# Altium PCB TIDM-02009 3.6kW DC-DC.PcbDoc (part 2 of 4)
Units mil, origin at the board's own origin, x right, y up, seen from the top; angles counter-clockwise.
Board outline 11220.47 x 8463 mil, 4 copper layers (Top Layer, Signal Layer 1, Signal Layer 2, Bottom Layer), stack 109.77 mil thick; 298 components, 250 nets, 959 pads, 2937 vias.
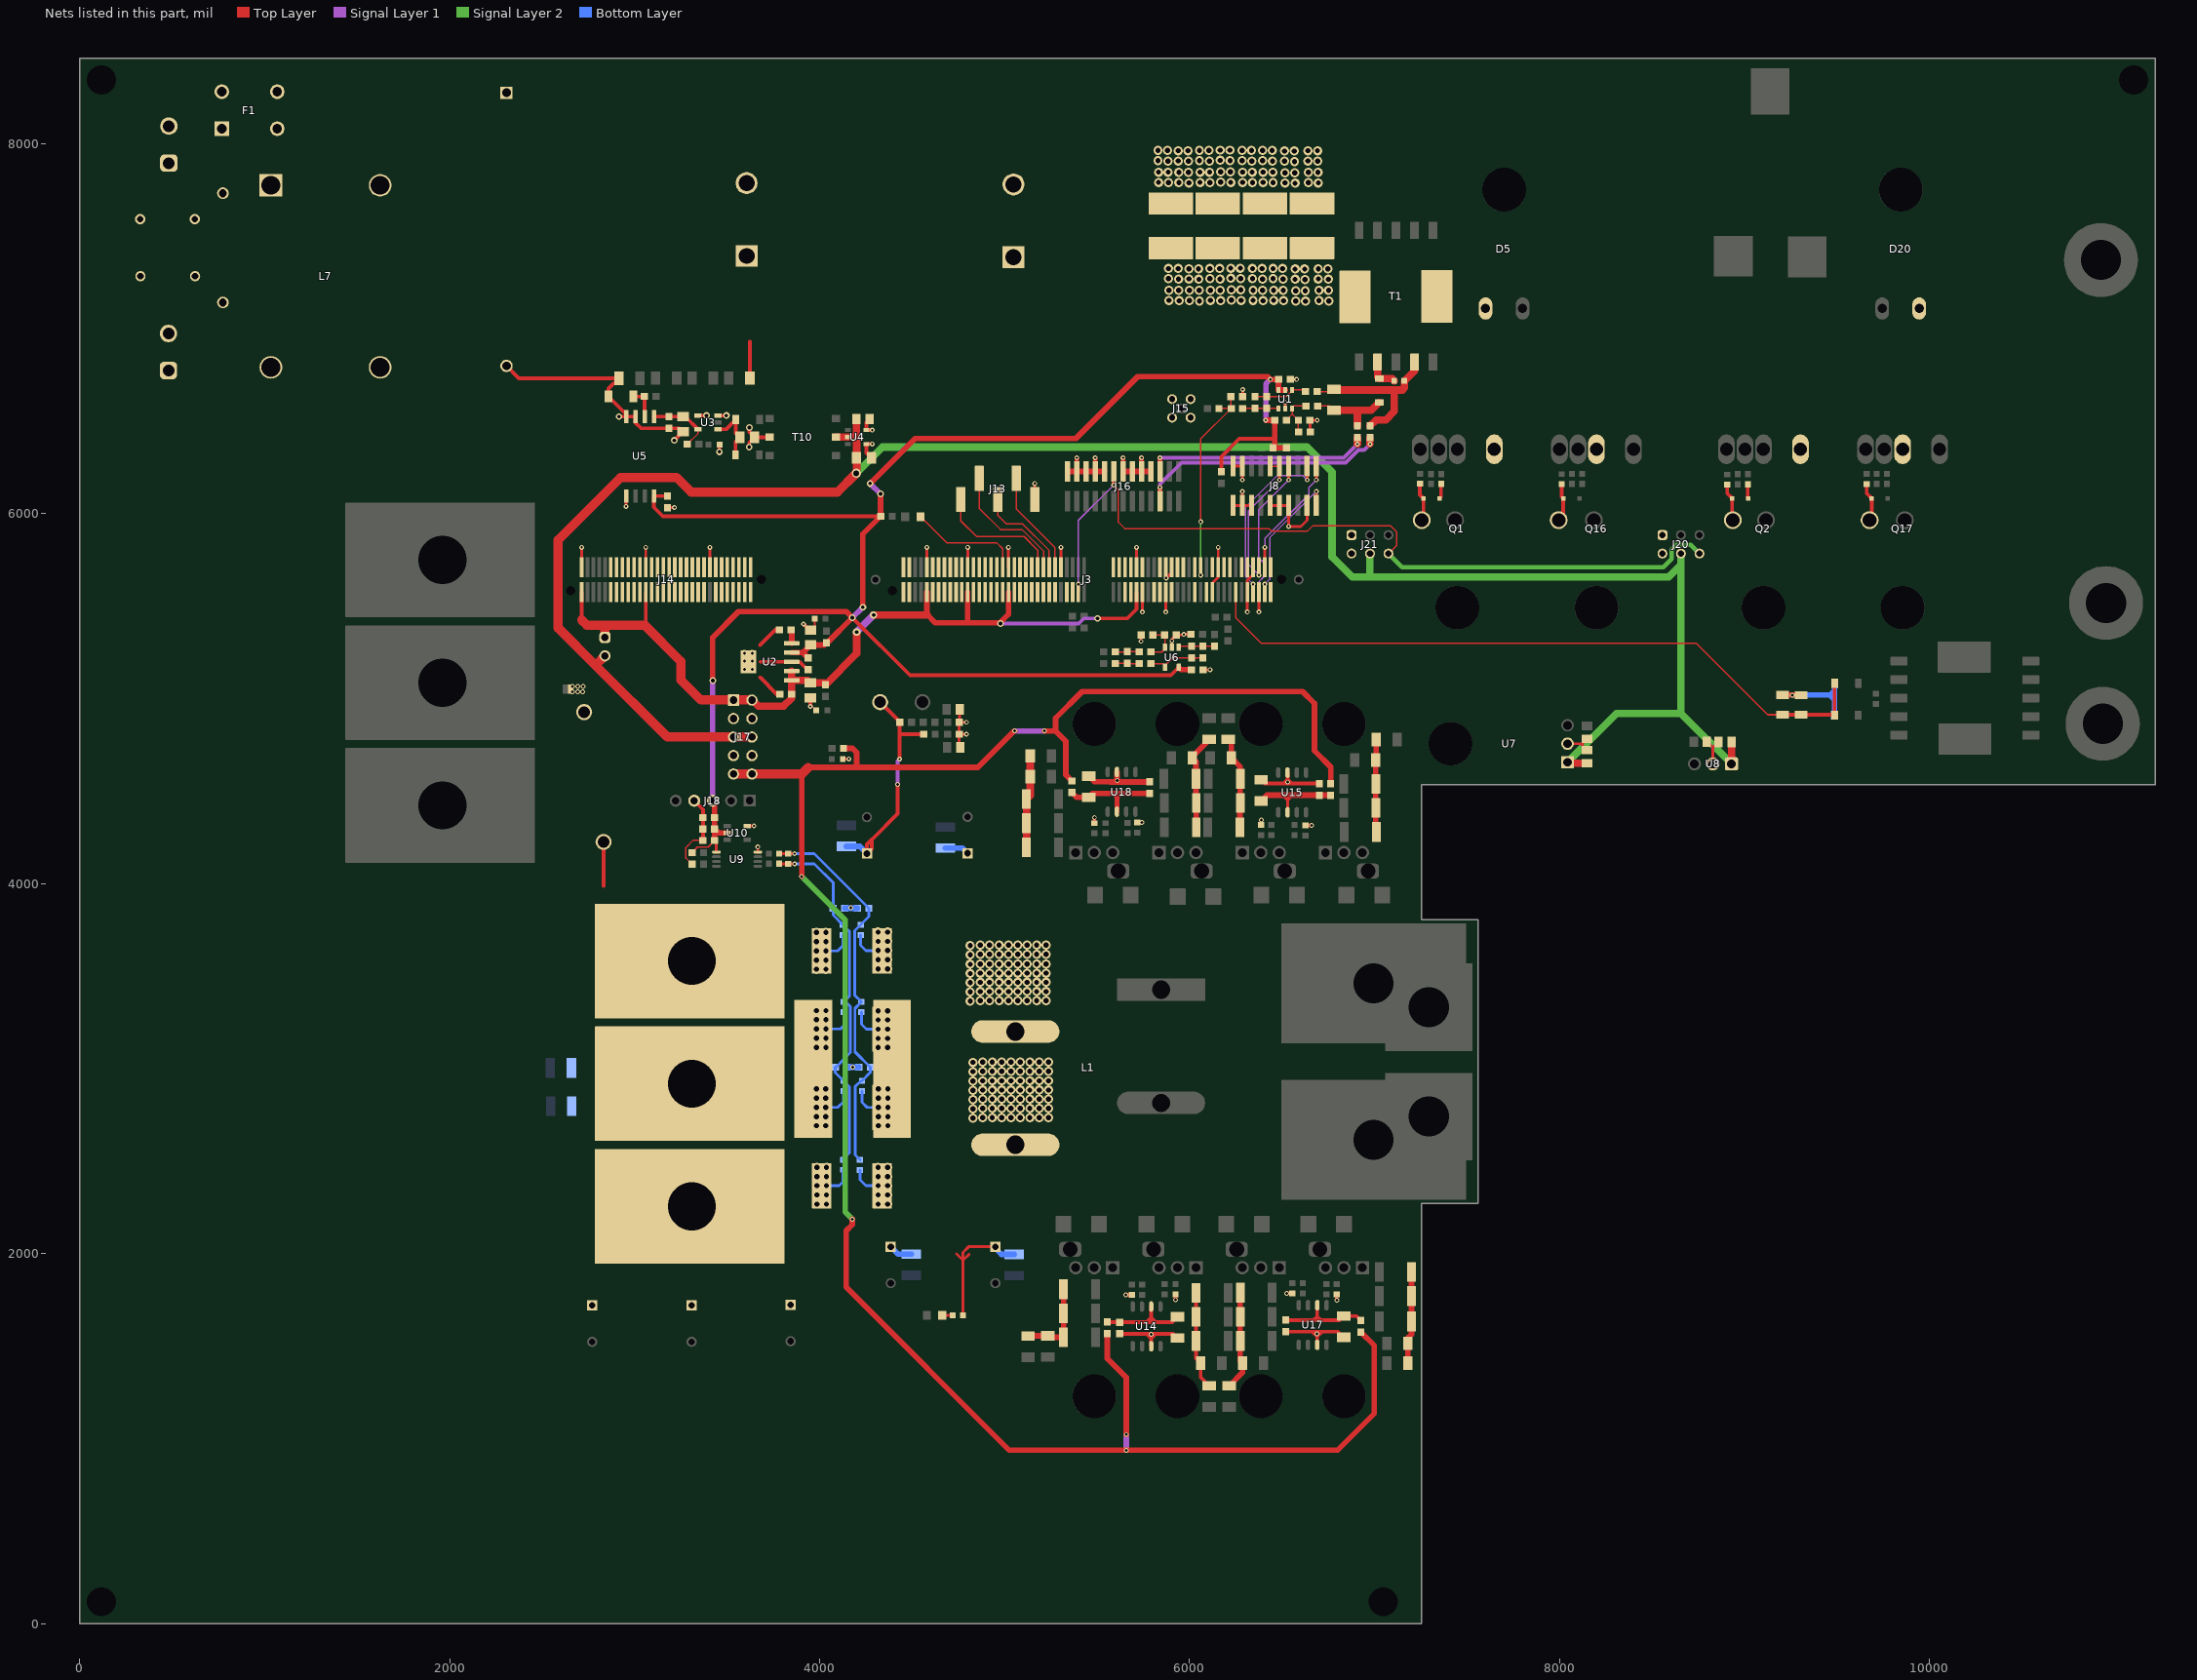
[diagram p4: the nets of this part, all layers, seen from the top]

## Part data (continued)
C52 C54 C55: library part CMP-0006982-4, "CAP, CERM, 220 pF, 50 V, +/- 10%, X7R, 0603", Cap_Case=0603, Manufacturer=Kemet, Supplier Part Number 1=399-5342-1-ND, TempCo=X7R, Tolerance_%=10%, Value1=Unknown, Value2=50V, ValueDisplayed=220pF
C64: library part CMP-0007143-4, "CAP, CERM, 0.01 uF, 50 V, +/- 10%, X7R, AEC-Q200 Grade 1, 0603", Cap_Case=0603, Manufacturer=MuRata, Supplier Part Number 1=490-4778-1-ND, TempCo=X7R, Tolerance_%=10%, Value1=Unknown, Value2=50V, ValueDisplayed=0.01uF
C65 C67 C73 C75: "CAP, CERM, 0.1 µF, 25 V,+/- 10%, X7R, AEC-Q200 Grade 1, 0603", Cap_Case=0603, Manufacturer=TDK, Supplier Part Number 1=445-5667-1-ND, TempCo=X7R, Tolerance_%=10, Value2=25V, ValueDisplayed=0.1µF
C66 C68 C74 C76: "CAP, CERM, 4.7 µF, 50 V, +/- 10%, X5R, 1206", Cap_Case=1206, Manufacturer=MuRata, Supplier Part Number 1=1845761, TempCo=X5R, Tolerance_%=10, Value1=Unknown, Value2=50V, ValueDisplayed=4.7µF
C83 C84: library part CMP-0083862-1, "CAP, AL, 120 µF, 600 V, +/- 20%, TH", Cap_Case=35x35mm, Manufacturer=Nichicon, Tolerance_%=20%, Value2=600V, ValueDisplayed=120µF
D1: "LED, Red, SMD", Color=Red, Manufacturer="Wurth Elektronik", Power_TotalModule=0.072, Supplier Part Number 1=732-4985-1-ND, Value1=0.072W, Value2=1.9V
D2: library part CMP-0029001-2, "Diode, Ultrafast, 100 V, 0.15 A, SOD-123", Manufacturer="Diodes Inc.", Value1=0.15A, Value2=1.25V
D3 D4 D18 D19: "Diode, Schottky, 40 V, 0.5 A, SOD-323", Manufacturer=Toshiba, Supplier Part Number 1=CUS05S40H3FCT-ND, Value1=0.5A, Value2=0.6V
D5 D20: library part CMP-0088257-2, "Diode Silicon Carbide Schottky 650V 37A (DC) Through Hole TO-220-2", Manufacturer=Wolfspeed
D6 D7 D8 D9 D10 D11 D12 D13: library part CMP-0087693-1, "70.1V Clamp 8.7A Ipp Tvs Diode Surface Mount DO-214AA (SMBJ)", Manufacturer=Littelfuse
D14 D15 D16 D17: library part 1N4148W-7-F, "Diode, Ultrafast, 100 V, 0.15 A, SOD-123", Manufacturer="Diodes Inc.", Supplier Part Number 1=1N4148W-FDICT-ND, Value1=0.15A, Value2=1.25V
D21 D27: library part CMP-0028526-1, "Diode, Schottky, 40 V, 0.5 A, SOD-123", Manufacturer="ON Semiconductor", Supplier Part Number 1=MBR0540T1GOSCT-ND, Value1=0.5A, Value2=0.51V
D22: library part CMP-0002951-1, "LED, Red, SMD", Color=Red, Manufacturer="Wurth Elektronik", Power_TotalModule=72mW, Supplier Part Number 1=732-4985-1-ND, Value1=0.072W, Value2=1.9V
D23 D24 D25 D26: library part CMP-0079921-1, "LED, Green, SMD", Color=Green, Manufacturer=Lite-On, Supplier Part Number 1=160-1828-1-ND, Value1=W, Value2=2V
F1: library part CMP-0088902-1, "FUSE HLDR CARTRIDGE 500V 16A PCB", Digikey Part Number=486-1160-ND, Fuse Current=16A, Manufacturer=Schurter, Mouser Part Number=693-3101.0045, Operating Temperature Range=to
"High Voltage1" "High Voltage2": library part CMP-0074835-1, "IEC 61010-1 High Voltage Warning"
J1 J2: library part CMP-0084907-1, "Terminal Block, 2 Pos, 5.08mm, Tin, TH", Color=Green, Current_A=20A, Manufacturer="Wurth Elektronik", Voltage_V=300V
J3: library part CMP-0003814-2, "C2000 controlCARD-120HSEC connector, SMT", Manufacturer=Samtec
J4 J5 J6 J7 J9 J10 J11 J12: library part CMP-0055026-1, Manufacturer=Mill-Max, Supplier Part Number 1=0312-015153427100-ND
J8: library part CMP-0075640-2, "Header, 1.27mm, 10x2, Tin, SMT", Color=Black, Current_A=3.1A, Manufacturer=Samtec, Supplier Part Number 1=SAM8792-ND
J13: library part CMP-0081122-1, "Header, 2.54mm, 5x1, Gold with Tin tail, SMT", Color=Black, Current_A=5.4A, Manufacturer=Samtec, Supplier Part Number 1=SAM12233-ND, Voltage_V=475V
J14: library part CMP-0003859-2, "C2000 controlCARD-180HSEC (60-pin addon) connector, SMT", Manufacturer=Samtec
J15: library part CMP-0088318-1, "MMCX Connector Jack, Female Socket 50Ohm Through Hole, Right Angle Solder", Dielectric Material=PTFE, Digikey Part Number=SAM10615-ND, Frequency_Fixed=6GHz, Manufacturer=Samtec, Mouser Part Number=200-MMCXJPHRATH1, Operating Temperature Range="-65°C to +125°C"
J16: library part CMP-0089180-1, Current_A=3.4A, Digikey Part Number=SAM9460-ND, Manufacturer=Samtec, Mouser Part Number=200-FTSH11301FDVK, Operating Temperature Range="-55°C to +125°C"
J17: library part CMP-0075665-2, "Header, 2.54mm, 5x2, Gold, Black, TH", Color=Black, Manufacturer=Samtec, Supplier Part Number 1=SAM8999-ND
J18: library part CMP-0075411-1, "Header, 100mil, 5x1, Gold, TH", Color=Black, Current_A=6.3A, Manufacturer=Samtec, Supplier Part Number 1=SAM1029-05-ND, Voltage_V=550V
J19: library part CMP-0084558-1, "Header, 2.54mm, 2x1, Tin, TH", Color=Black, Current_A=6.3A, Manufacturer=Samtec, Voltage_V=550V
J20 J21: library part CMP-0082603-1, "Receptacle, 2.54mm, 3x2, Tin, TH", Color=Green, Manufacturer="TE Connectivity", Supplier Part Number 1=A106656-ND
L1: library part CMP-0088176-1, "Fixed Inductor of Cyntec", Manufacturer=Cyntec
L2: library part CMP-0060854-1, "Inductor, Shielded E Core, Ferrite, 4.7 uH, 30 A, 0.00186 ohm, SMD", Manufacturer=Coilcraft, Value1="0.00186 ohm", Value2=30A, ValueDisplayed=4.7uH
L3 L4 L5 L6: "Ferrite Bead, 120 ohm @ 100 MHz, 0.5 A, 0603", Manufacturer="Wurth Elektronik", Supplier Part Number 1=732-1594-1-ND, Value1="0.3 ohm", Value2=0.5A, ValueDisplayed="120 ohm"
L7: "CMC 2.5MH 25A 2LN TH", Manufacturer="Wurth Elektronik", PartNumber=7448052502, Supplier Part Number 1=732-5600-ND, ValueDisplayed=2.5mH
LBL1: library part CMP-0003625-1, "Thermal Transfer Printable Labels, 0.650\" W x 0.200\" H - 10,000 per roll", Manufacturer=Brady, Supplier Part Number 1=97C5133
NT1: library part CMP-0078142-2, "Single point connection between nets.", Manufacturer=N/A
Q1 Q2 Q16 Q17: library part CMP-0088256-2, "SiC N-Channel MOSFET, 35 A, 1000 V C3M, 4-Pin TO-247", Manufacturer=Wolfspeed
R1: "RES, 13.0 k, 1%, 0.1 W, 0603", Manufacturer="Yageo America", Power_W=0.1, Supplier Part Number 1=311-13.0KHRCT-ND, TempCo="200 ppm/C", Tolerance_%=1, Value1=1%, Value2=0.1W, Value_Code=13k0, ValueDisplayed=13.0k
R2 R3 R4 R5 R15 R17 R18 R20: "RES, 10.0, 1%, 0.1 W, 0603", Manufacturer=Vishay-Dale, Power_W=0.1, Supplier Part Number 1=541-10.0HCT-ND, TempCo="100 ppm/C", Tolerance_%=1, Value1=1%, Value2=0.1W, Value_Code=10R0, ValueDisplayed=10.0
R6 R7 R8 R9: library part CMP-0087912-1, "500 µOhms ±1% 9W Chip Resistor Nonstandard Current Sense, Pulse Withstanding", Manufacturer=Cyntec, Power_W=9W, TempCo=75ppm/°C, Tolerance_%=1%
R10 R13: "RES, 0, 5%, 0.1 W, 0603", Manufacturer=Vishay-Dale, Power_W=0.1, Supplier Part Number 1=541-0.0GCT-ND, TempCo="200 ppm/C", Tolerance_%=5, Value1=5%, Value2=0.1W, Value_Code=0000, ValueDisplayed=0
R11: library part CMP-0087913-1, "125uOhm, 15W, high power, low ESL current shunt resistor", Manufacturer=Cyntec, Power_W=15W, TempCo=100ppm/°C, Tolerance_%=1%
R12 R68 R74 R79 R83 R87 R91 R92: library part CMP-0081973-1, "RES, 0, 0%, 0.25 W, AEC-Q200 Grade 0, 0603", Manufacturer=Vishay-Dale, Power_W=250mW, Supplier Part Number 1=541-2779-1-ND, Tolerance_%=0%, Value2=0.25W, Value_Code=0
R14 R43: "RES, 100 k, 1%, 0.1 W, 0603", Manufacturer=Vishay-Dale, Power_W=0.1, Supplier Part Number 1=541-100KHCT-ND, TempCo="100 ppm/C", Tolerance_%=1, Value1=1%, Value2=0.1W, Value_Code=100k
R16: library part CMP-0022679-3, "RES, 100, 1%, 0.1 W, AEC-Q200 Grade 0, 0603", Manufacturer=Panasonic, Power_W=100mW, Supplier Part Number 1=P100HCT-ND, TempCo="100 ppm/C", Tolerance_%=1%, Value2=0.1W, Value_Code=100R, ValueDisplayed=100
R19 R39: library part CMP-0023153-5, "RES, 4.70 k, 1%, 0.1 W, 0603", Manufacturer=Yageo, Power_W=100mW, Supplier Part Number 1=311-4.70KHRCT-ND, TempCo="100 ppm/C", Tolerance_%=1%, Value2=0.1W, Value_Code=4k70, ValueDisplayed=4.70k
R21 R22 R64 R65: "RES, 5.11, 1%, 0.1 W, 0603", Manufacturer=Vishay-Dale, Power_W=0.1, Supplier Part Number 1=541-5.11HHCT-ND, TempCo="100 ppm/C", Tolerance_%=1, Value1=1%, Value2=0.1W, Value_Code=5R11, ValueDisplayed=5.11
R23 R24 R69 R70: "RES, 1.00, 1%, 0.1 W, 0603", Manufacturer="Yageo America", Power_W=0.1, Supplier Part Number 1=311-1.00HRCT-ND, TempCo="200 ppm/C", Tolerance_%=1, Value1=1%, Value2=0.1W, Value_Code=1R00, ValueDisplayed=1.00
R25 R26 R71 R72 R157 R158 R159 R160 R172 R173 R174 R175: "RES, 10.0 k, 1%, 0.1 W, 0603", Manufacturer=Vishay-Dale, Power_W=0.1, Supplier Part Number 1=541-10.0KHCT-ND, TempCo="100 ppm/C", Tolerance_%=1, Value1=1%, Value2=0.1W, Value_Code=10k0, ValueDisplayed=10.0k
R27 R28 R29 R30 R31 R32 R33 R34 R35 R36 R37 R38 R44 R45 R46 R47 R48 R49 R50 R51 R52 R53 R54 R55: "RES, 30, 5%, 0.75 W, AEC-Q200 Grade 0, 2010", Manufacturer=Vishay-Dale, Power_W=0.75, Supplier Part Number 1=541-30.0WCT-ND, TempCo="200 ppm/C", Tolerance_%=5, Value1=5%, Value2=0.75W, Value_Code=30R0, ValueDisplayed=30
R40 R59: library part CMP-0023143-5, "RES, 49.9, 1%, 0.1 W, 0603", Manufacturer=Yageo, Power_W=100mW, Supplier Part Number 1=311-49.9HRCT-ND, TempCo="100 ppm/C", Tolerance_%=1%, Value2=0.1W, Value_Code=49R9, ValueDisplayed=49.9
R41 R56 R67: library part CMP-0022895-5, "RES, 1.00 k, 1%, 0.1 W, 0603", Manufacturer=Yageo, Power_W=100mW, Supplier Part Number 1=311-1.00KHRCT-ND, TempCo="100 ppm/C", Tolerance_%=1%, Value2=0.1W, Value_Code=1k00, ValueDisplayed=1.00k
R42 R57 R88 R95 R96 R140: library part CMP-0022746-5, "RES, 10.0 k, 1%, 0.1 W, 0603", Manufacturer=Yageo, Power_W=100mW, Supplier Part Number 1=311-10.0KHRCT-ND, TempCo="100 ppm/C", Tolerance_%=1%, Value2=0.1W, Value_Code=10k0, ValueDisplayed=10.0k
R58: library part CMP-0022751-4, "RES, 10.0, 1%, 0.1 W, 0603", Manufacturer=Yageo, Power_W=100mW, Supplier Part Number 1=311-10.0HRCT-ND, TempCo="100 ppm/C", Tolerance_%=1%, Value2=0.1W, Value_Code=10R0, ValueDisplayed=10.0
R60 R61: library part CMP-0018067-2, "RES, 20.0, 1%, 0.25 W, 1206", Manufacturer="Yageo America", Power_W=250mW, Supplier Part Number 1=311-20.0FRCT-ND, TempCo="100 ppm/C", Tolerance_%=1%, Value2=0.25W, Value_Code=20R0, ValueDisplayed=20.0
R62: library part CMP-0017094-3, "RES, 5.36, 1%, 0.25 W, AEC-Q200 Grade 0, 1206", Manufacturer=Vishay-Dale, Power_W=250mW, Supplier Part Number 1=541-5.36FFCT-ND, TempCo="100 ppm/C", Tolerance_%=1%, Value2=0.25W, Value_Code=5R36, ValueDisplayed=5.36
R63 R86: library part CMP-0022982-5, "RES, 2.15 k, 1%, 0.1 W, 0603", Manufacturer=Yageo, Power_W=100mW, Supplier Part Number 1=311-2.15KHRCT-ND, TempCo="100 ppm/C", Tolerance_%=1%, Value2=0.1W, Value_Code=2k15, ValueDisplayed=2.15k
R66: library part CMP-0022692-3, "RES, 22.0 k, 1%, 0.1 W, AEC-Q200 Grade 0, 0603", Manufacturer=Panasonic, Power_W=100mW, Supplier Part Number 1=P22.0KHCT-ND, TempCo="100 ppm/C", Tolerance_%=1%, Value2=0.1W, Value_Code=22k0, ValueDisplayed=22.0k
R73: library part CMP-0022865-5, "RES, 1.05 k, 1%, 0.1 W, 0603", Manufacturer=Yageo, Power_W=100mW, Supplier Part Number 1=311-1.05KHRCT-ND, TempCo="100 ppm/C", Tolerance_%=1%, Value2=0.1W, Value_Code=1k05, ValueDisplayed=1.05k
R75: library part CMP-0021989-3, "RES, 4.99 k, 1%, 0.1 W, 0603", Manufacturer=Bourns, Power_W=100mW, Supplier Part Number 1=CR0603-FX-4991ELFTR-ND, TempCo="100 ppm/C", Tolerance_%=1%, Value2=0.1W, Value_Code=4k99, ValueDisplayed=4.99k
R76 R77 R78: library part CMP-0017741-3, "RES, 845 k, 1%, 0.25 W, AEC-Q200 Grade 0, 1206", Manufacturer=Panasonic, Power_W=250mW, Supplier Part Number 1=P845KFCT-ND, TempCo="100 ppm/C", Tolerance_%=1%, Value2=0.25W, Value_Code=845k
R80: library part CMP-0017754-3, "RES, 9.09 k, 1%, 0.25 W, AEC-Q200 Grade 0, 1206", Manufacturer=Panasonic, Power_W=250mW, Supplier Part Number 1=P9.09KFCT-ND, TempCo="100 ppm/C", Tolerance_%=1%, Value2=0.25W, Value_Code=9k09, ValueDisplayed=9.09k
R81 R94: library part CMP-0022816-5, "RES, 15.0 k, 1%, 0.1 W, 0603", Manufacturer=Yageo, Power_W=100mW, Supplier Part Number 1=311-15.0KHRCT-ND, TempCo="100 ppm/C", Tolerance_%=1%, Value2=0.1W, Value_Code=15k0, ValueDisplayed=15.0k
R82 R84 R85 R93: library part CMP-0023151-5, "RES, 4.64 k, 1%, 0.1 W, 0603", Manufacturer=Yageo, Power_W=100mW, Supplier Part Number 1=311-4.64KHRCT-ND, TempCo="100 ppm/C", Tolerance_%=1%, Value2=0.1W, Value_Code=4k64, ValueDisplayed=4.64k
R89: library part CMP-0023250-5, "RES, 6.49 k, 1%, 0.1 W, 0603", Manufacturer=Yageo, Power_W=100mW, Supplier Part Number 1=311-6.49KHRCT-ND, TempCo="100 ppm/C", Tolerance_%=1%, Value2=0.1W, Value_Code=6k49, ValueDisplayed=6.49k
R90: library part CMP-0022684-3, "RES, 10.0 k, 1%, 0.1 W, 0603", Manufacturer=Panasonic, Power_W=100mW, Supplier Part Number 1=P10.0KHCT-ND, TempCo="100 ppm/C", Tolerance_%=1%, Value2=0.1W, Value_Code=10k0, ValueDisplayed=10.0k
R152 R153 R155 R156 R168 R169 R170 R171: "RES, 2.21, 1%, 0.1 W, 0603", Manufacturer=Vishay-Dale, Power_W=0.1, Supplier Part Number 1=541-2.21HHCT-ND, TempCo="100 ppm/C", Tolerance_%=1, Value1=1%, Value2=0.1W, Value_Code=2R21, ValueDisplayed=2.21
SR1 SR2 SR3 SR4 SR5 SR6 SR7 SR8: library part CMP-0087973-1, "MOSFET N-CH TO220-3", Manufacturer="Infineon Technologies"
T1 T8: library part CMP-0085494-1, "Current Sense Transformer, 8.5 mH, 254 Vµs, 40 A, AEC-Q200 Grade 1, SMT", Manufacturer=Coilcraft, ValueDisplayed=8.5mH
T2 T3 T4 T5 T7 T9: library part CMP-0077156-1, "Terminal 125A Lug", Current_A=125A, Manufacturer=Panduit, Supplier Part Number 1=298-11598-ND, Voltage_V=600V
T10: library part CMP-0030718-1, "Transformer, 475uH, SMT", Manufacturer="Wurth Elektronik", Supplier Part Number 1=732-4458-1-ND, ValueDisplayed=475uH
TP1 TP4: library part CMP-0055142-1, "Test Point, Compact, Red, TH", Color=Red, Manufacturer=Keystone, Supplier Part Number 1=36-5005-ND
TP2 TP3: library part CMP-0055155-1, "Test Point, Compact, Blue, TH", Color=Blue, Manufacturer=Keystone, Supplier Part Number 1=36-5122-ND
U1: library part CMP-0040148-1, "Very Low Power, Rail to Rail Out, Negative Rail In, VFB Operational Amplifier, 2.5 to 5.5 V, -40 to 125 degC, 6-pin SOT23 (DBV6), Green (RoHS & no Sb/Br)", Manufacturer="Texas Instruments"
U2: library part CMP-0036711-1, "Single Output High PSRR LDO, 1 A, Fixed 3.3 V Output, 2.7 to 5.5 V Input, 6-pin SOT-223 (DCQ), -40 to 125 degC, Green (RoHS & no Sb/Br)", Manufacturer="Texas Instruments"
U3: library part CMP-0077327-2, "40-V Ultralow-Iq Low-Dropout Regulator, DBV0005A (SOT-23-5)", Alternate Manufacturer="Texas Instruments"
U4: library part CMP-0076093-1, "Automotive Low-Noise 350 mA, 410 kHz Transformer Driver, DBV0005A (SOT-23-5)", Alternate Manufacturer="Texas Instruments"
U5: library part CMP-0078341-1, "Precision, 2-V Input, Reinforced Isolated Amplifier, DWV0008A (SOIC-8)", Alternate Manufacturer="Texas Instruments", Alternate PartNumber=AMC1311BDWV
U6: library part CMP-0041002-2, "50 MHz, Low-Noise, Single-Supply Rail-to-Rail Operational Amplifier, 2.2 to 5.5 V, -40 to 125 degC, 5-pin SOT23 (DBV5), Green (RoHS & no Sb/Br)", Manufacturer="Texas Instruments", Total Supply Voltage(Max)(+5V is 5, +/-5V is 10)=5.5, Total Supply Voltage(Min)(+5V is 5, +/-5V is 10)=2.2
U7: library part CMP-0089136-1, "Temperature Sensor Analog, Local 0°C ~ 100°C 10mV/°C TO-220-3", Digikey Part Number=LM35DT/NOPB-ND, Manufacturer="Texas Instruments", Max Supply Voltage=30V, Min Supply Voltage=4V, Mouser Part Number=926-LM35DT/NOPB, Operating Supply Current=56-91.5uA, Operating Temperature Range="0°C to +100°C", Output Voltage=6V
U8: library part CMP-0073408-4, "Precision Centigrade Temperature Sensor, 3-pin TO-220, Pb-Free", Manufacturer="Texas Instruments", PackageTopMarking=NSUZXYTTE#*LM35DT, PowerWise=N
U9: library part CMP-0075735-1, "High/Low Side, Bi-Directional Zero-Drift Current Sense Amp w/ Enhanced PWM Rejection, PW0008A (TSSOP-8)", Alternate Manufacturer="Texas Instruments", Alternate PartNumber=INA240A2PW
U10: library part CMP-0860809-1, "Automotive, 110-V Common-Mode, High-Voltage, High-Bandwidth, Zero-Drift, Unidirectional, Current-Sense Amplifier, DBV0005A (SOT-23-5)", Alternate Manufacturer="Texas Instruments"
U14 U15 U17 U18: library part CMP-0073915-1, "Automotive grade Dual 5-A High-Speed Low-Side Gate Driver With Negative Input Voltage Capability, D0008A (SOIC-8)", Alternate Manufacturer="Texas Instruments"
ZZ1: library part CMP-0003616-3
ZZ2: library part CMP-0077236-1
ZZ3: library part CMP-0077237-1
ZZ4: library part CMP-0077238-1

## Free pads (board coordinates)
  rrect50% 120x70 hole 157.48: 0(118.11,118.11) 0(118.11,8344.89) 0(11102.36,8344.89)
  rrect50% 39.37x70 hole 157.48: 0(7047.24,118.11)
  rect 1000x620 all layers, no hole: 1(1961.56,4423.45) 1(1961.56,5086.97) 1(1961.56,5750.49) 1(3309.56,2255.45) 1(3309.56,2918.97) 1(3309.56,3582.49)
  round 400 hole 216.53: 1(10954,5518) 2(10926,7372) 2(10936,4865)
  rect 1000x650 hole 216.53: 3(6994.55,2615.56) 4(6994.55,3462.02)
  rect 472.44x472.44 hole 216.53: 3(7293,2741.7) 4(7293,3332.25)
  rrect50% 120x80 hole 80 square: 5(5354.58,2024) 5(5614.58,4068.79) 5(5804.48,2024) 5(6064.48,4068.79) 5(6254.38,2024) 5(6514.38,4068.79) 5(6704.28,2024) 5(6964.28,4068.79)

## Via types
v1: diameter 50, hole 28, Top Layer to Bottom Layer, 2769 vias
v2: diameter 26, hole 12, Top Layer to Bottom Layer, 96 vias
v3: diameter 26, hole 16, Top Layer to Bottom Layer, 49 vias
v4: diameter 36, hole 20, Top Layer to Bottom Layer, 14 vias
v5: diameter 34, hole 16, Top Layer to Bottom Layer, tented both sides, 6 vias
v6: diameter 40, hole 20, Top Layer to Bottom Layer, 2 vias
v7: diameter 50, hole 30, Top Layer to Bottom Layer, 1 vias

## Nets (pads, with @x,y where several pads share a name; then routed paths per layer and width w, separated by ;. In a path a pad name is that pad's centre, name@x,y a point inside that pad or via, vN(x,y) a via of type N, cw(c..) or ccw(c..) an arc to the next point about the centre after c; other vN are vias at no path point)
5V_IPS: C45.1 C47.1 C56.1 C57.1 J17.5 J17.6 J19.2 J20.4 J21.4 T10.2 U4.2 U7.1 U8.1 | length 11502.1
  Top Layer w40: T10.2@4089,6415 U4.2@4152.8,6415 4191,6415 4198.57,6407.43 ; C47.1@4198.57,6512 4198.57,6407.43 ; v7@4200,6221 C45.1@4200,6303 4200,6406 4198.57,6407.43 ; U7.1@8043,4657 8048.43,4651.57 C57.1@8148,4651.57 ; U8.1@8929,4648 8929.43,4648.43 C56.1@8929.43,4767
  Top Layer w50: J19.2@2839.58,5232 2788.79,5181.2 2788.79,5180.79 ; J17.6@3634,4793 J17.5@3534,4793 3176.57,4793 2788.79,5180.79 ; v7@4200,6221 v7(4198,6219) 4096,6117 3306.16,6117 3227.16,6196 2924,6196 2587,5859 2587,5382.57 2788.79,5180.79
  Signal Layer 2 w40: v7(4198,6219) 4340,6361 6634,6361 6770,6225 6770,5767 6879,5658 6975,5658 ; J21.4@6975,5785 6975,5658 ; U7.1@8043,4657 8307,4921 8656,4921 ; J20.4@8656,5785 8656,5724 ; U8.1@8929,4648 8656,4921 ; 6975,5658 8590,5658 8656,5724 ; 8656,4921 8656,5724
5Vs: C60.1 C61.1 J3.48 J3.84 J3.98 J3.112 J14.158 J14.180 J17.1 J17.2 J19.1 R140.2 U2.1 U2.2 | length 4674.9
  Top Layer w20: 2713.6,5426 J14.180@2713.6,5577.14 ; 3053.76,5397.95 3060.05,5397.95 J14.158@3060.05,5577.14 ; v4@4974,5410 v4(4977,5407) ; v4(5502,5434) 5663,5434 5713.6,5484.6 J3.48@5713.6,5577.14
  Top Layer w30: J3.112@4579.74,5577.14 4579.74,5456.26 4626,5410 4800.06,5410 ; J3.98@4800.21,5577.14 4800.21,5410.15 4800.06,5410 ; J3.84@5020.69,5577.14 5020.69,5456.69 4974,5410 4800.06,5410
  Top Layer w40: J17.2@3634,4993 3668,4959 3804.63,4959 3848,5002.37 C61.1@3848,5025 3848,5148.87 U2.2@3849.13,5150 ; U2.1@3849.13,5100 3936,5100 C60.1@3950,5086 4022.5,5086 R140.2@4032,5076.5 4200,5244.5 v6(4200,5361) ; v6(4292,5453) 4576.48,5453 4579.74,5456.26
  Top Layer w50: 2713.6,5426 2741.65,5397.95 2839.58,5397.95 ; J19.1@2839.58,5332 2839.58,5397.95 ; J17.2@3634,4993 J17.1@3534,4993 3358,4993 3250,5101 3250,5201.7 3053.76,5397.95 2839.58,5397.95
  Signal Layer 1 w20: v4(4977,5407) 5401,5407 5428,5434 v4(5502,5434)
  Signal Layer 1 w40: v6(4200,5361) v6(4292,5453)
12Vout: C14.1 C15.1 C44.1 C71.1 C72.1 pad.1@3309.56,2255.45 pad.1@3309.56,2918.97 pad.1@3309.56,3582.49 R6.1 R7.1 R8.1 R9.1 R11.1 R15.1 R17.1 R18.1 R20.1 T5.1 T7.1 T9.1 TP4.1 | length 907.2
  Top Layer w20: 2832,3987 TP4.1@2832,4226
  Bottom Layer w15: v1(4033,2791) 4098,2791 4129,2822 R18.1@4129,2880 ; v1(4034,3215) 4113,3215 4130,3232 R17.1@4130,3306.44 ; v1(4034,3637.21) 4098.21,3637.21 4125,3664 R15.1@4125,3722.88 ; v1(4037,2367.5) 4105.5,2367.5 4126,2388 R20.1@4126,2453.44
  other v1: 3986,2268 4037,2268 3986,2317.75 4037,2317.75 3986,2367.5 3986,2417.25 4037,2417.25 3986,2467 4037,2467 3982,2691.5 4033,2691.5 3982,2741.25 4033,2741.25 3982,2791 3982,2840.75 4033,2840.75 3982,2890.5 4033,2890.5 3983,3115.5 4034,3115.5 3983,3165.25 4034,3165.25 3983,3215 3983,3264.75 4034,3264.75 3983,3314.5 4034,3314.5 3983,3537.71 4034,3537.71 3983,3587.46 4034,3587.46 3983,3637.21 3983,3686.96 4034,3686.96 3983,3736.71 4034,3736.71
+3V3: C1.1 C2.1 C4.1 C50.1 C53.1 C62.1 C63.1 C70.1 J18.3 R16.1 R19.2 R39.1 R66.2 R88.2 R89.2 R95.2 U1.5 U1.6 U2.4 U5.8 U6.5 U9.5 U10.2 | length 10347.5
  Top Layer w8: R89.2@3309.5,4168 3340.08,4198.57 3397.07,4198.57 C70.1@3432.5,4234
  Top Layer w15: C70.1@3432.5,4234 3441.8,4224.7 U9.5@3441.8,4171.39
  Top Layer w20: C50.1@3178,6096.5 3177.94,6096.43 U5.8@3104,6096.43 3104,6035 3152,5987 R95.2@4329.5,5987 ; v4(4177,5438.41) 4488.41,5127 5898.54,5127 U6.5@5941.4,5169.87 ; R19.2@6171,6227.5 6171,6309 6268,6406 6460.01,6406
  Top Layer w30: J18.3@3422,4449 3432.5,4438.5 C2.1@3432.5,4358 C1.1@3432.5,4296 ; v4(3422,5099) 3422,5332 3561,5471 4144.41,5471 v4(4177,5438.41) 4041.09,5302.5 R88.2@4036,5302.5 4024.5,5291 C62.1@3951,5291 3910,5250 3908.5,5250 ; C70.1@3432.5,4234 C1.1@3432.5,4296 ; U10.2@3500.87,4275 3453.5,4275 C1.1@3432.5,4296 ; U2.4@3849.13,5250 3908.5,5250 ; C63.1@3938,5220.5 3908.5,5250 ; v4(4233.59,5495) 4233.59,5891.08 R95.2@4329.5,5987 v4(4329.5,6107.5) ; v4(4273.01,6164) 4516.01,6407 5385,6407 5720,6742 6420.5,6742 v2(6436,6726.5) C4.1@6480.5,6726.5 6479.6,6725.59 U1.6@6479.6,6669.69 U1.5@6517,6669.69 ; U6.5@5941.4,5169.87 5954.27,5157 C53.1@6010.5,5157 ; v2(6412,6506) 6459.5,6506 R66.2@6460.01,6505.5 R39.1@6460.01,6368 ; 6460.01,6406 6460.01,6366.01 R39.1@6451,6357 R16.1@6522.5,6357
  Signal Layer 1 w30: J18.3@3422,4449 v4(3422,5099) ; v4(4177,5438.41) v4(4233.59,5495) ; v4(4273.01,6164) v4(4329.5,6107.5) ; v2(6412,6506) 6412,6702.5 v2(6436,6726.5)
+12V: J17.9 J17.10 L3.1 L4.1 L5.1 L6.1 R96.2 | length 11677.7
  Top Layer w30: v3(3903,4040) 3903,4593 ; 3939,4629 4200,4629 ; R96.2@4128.97,4732 4178,4732 4200,4710 4200,4629 ; v3(4176,2187) 4176,2157 4143.13,2124.13 4143.13,1819.83 5025.52,937.44 v3(5657.52,937.44) 6799.52,937.44 6998.52,1136.44 6998.52,1502.94 L5.1@6924.52,1576.94 ; v3(5054,4826) 5052,4826 4855,4629 4200,4629 ; v3(5215,4826) 5275,4826 ; L6.1@5364,4555.5 5331,4588.5 5331,4770 5275,4826 ; L3.1@5554.52,1566.94 5554.52,1433.44 5657.52,1330.44 v3(5657.52,1022.44) ; L4.1@6763,4541.5 6763,4630.39 6675,4718.39 6675,4975 6610.87,5039.13 5419.13,5039.13 5275,4895 5275,4826
  Top Layer w50: J17.9@3534,4593 J17.10@3634,4593 3903,4593 3939,4629
  Signal Layer 1 w30: v3(5054,4826) v3(5215,4826) ; v3(5657.52,937.44) v3(5657.52,1022.44)
  Signal Layer 2 w30: v3(3903,4040) 4138,3805 4138,2225 v3(4176,2187)
ADC_A0A1_N: J3.11
ADC_A0A1_P: J3.9
ADC_A2A3_N: J3.17
ADC_A2A3_P: J3.15
ADC_A4A5_P: J3.21
ADC_B4B5_P: J3.24
ADC_C2C3_N: J3.33
ADC_C2C3_P: J3.31
ADC_C4C5_N: J3.39
ADC_C4C5_P: J3.37
ADC_D0D1_P: J3.28
ADC_D2D3_N: J3.36
ADC_D4D5_N: J3.42
ADC_D4D5_P: J3.40
ADC_IN1415_N: J3.27
AGND: C1.2 C2.2 C4.2 C6.2 C7.2 C12.2 C13.2 C39.2 C40.2 C41.2 C42.2 C45.2 C47.2 C50.2 C53.2 C54.2 C55.2 C56.2 C57.2 C58.2 C59.2 C60.2 C61.2 C62.2 C63.2 C64.2 C65.2 C66.2 C67.2 C68.2 C70.2 C73.2 C74.2 C75.2 C76.2 D15.2 D17.2 D24.2 D25.2 D26.2 J3.7 J3.10 J3.19 J3.22 J3.35 J3.38 J3.46 J3.47 J3.65 J3.83 J3.97 J3.111 J8.4 J8.8 J8.10 J8.12 J8.16 J8.17 J8.18 J8.19 J8.20 J13.1 J14.135 J14.157 J14.179 J15.2 J15.3 J15.4 J15.5 J16.7 J16.9 J16.11 J16.13 J16.17 J16.19 J16.21 J16.23 J16.25 J17.3 J17.4 J17.7 J17.8 J18.4 J20.1 J20.2 J21.1 J21.2 NT1.2 R60.2 R61.2 R63.1 R73.1 R86.1 R90.1 R94.1 R157.1 R158.1 R159.1 R160.1 R172.1 R173.1 R174.1 R175.1 TP1.1 U1.2 U2.3 U2.6 U4.4 U4.5 U5.5 U6.2 U7.2 U8.2 U9.4 U10.5 U14.3 U15.3 U17.3 U18.3 | length 8504.9
  Top Layer w8: R90.1@3309.5,4106 3277,4138.5 3277,4196 3315,4234 C70.2@3369.5,4234 ; v2(3950,4959) 3960.47,4959 D26.2@3982.47,4937 ; C62.2@3951,5371 3973.47,5393.47 D25.2@3973.47,5433
  Top Layer w15: J14.179@2713.6,5711 v2(2713.6,5818.95) ; v2(2954,6040) U5.5@2954,6096.43 ; J14.157@3060.05,5711 v2(3060.05,5818.95) ; C50.2@3178,6033.5 v2(3215.5,6033.5) ; J14.135@3406.51,5711 v2(3406.51,5818.95) ; U10.5@3609.13,4312.4 v2(3645.4,4312.4) ; U9.4@3666.2,4171.39 v2(3666.2,4198.8) ; D24.2@4125,4675 v2(4158.47,4675) ; J3.111@4579.74,5711 v2(4579.74,5818.95) ; R86.1@4753.98,4809 v2(4793.99,4809) ; C39.2@4757,4943 4757,4876.01 R63.1@4753.99,4873 ; C40.2@4759.43,4737 4753.99,4742.44 R86.1@4753.99,4808 R63.1@4753.99,4873 ; v2(4794,4873) R63.1@4753.99,4873 ; J3.97@4800.21,5711 v2(4800.21,5818.95) ; J3.83@5020.69,5711 v2(5020.69,5818.95) ; J13.1@5163,6077 v2(5163,6164) ; J3.65@5304.15,5711 v2(5304.15,5818.95) ; J3.47@5713.6,5711 v2(5713.6,5818.95) ; v2(5737.5,5310.5) C55.2@5737.5,5345 ; v2(5745.09,5469.2) J3.46@5745.09,5577.14 ; v2(5871.08,5469.2) J3.38@5871.08,5577.14 ; v2(5873,5653) 5902.58,5682.58 J3.35@5902.58,5711 ; U6.2@5904,5278.13 v2(5904,5313) 5904,5321.5 R94.1@5927.5,5345 5966,5345 v2(5969,5348) C54.2@6007.5,5348 ; C53.2@6073.5,5157 v2(6110,5157) ; J3.22@6123.05,5577.14 6123.05,5625.5 6143.57,5646.02 6144.02,5646.02 6154.54,5656.54 J3.19@6154.54,5711 v2(6154.54,5818.95) ; J8.20@6235,6045.01 J8.18@6285,6045.01 ; J8.19@6235,6258 J8.17@6285,6258 v2(6285,6183.01) ; v2(6285,6120) J8.18@6285,6045.01 ; C41.2@6286.99,6633.5 v2(6286.99,6671.99) ; v2(6312.02,5469.2) J3.10@6312.02,5577.14 6312.02,5640.02 6343.52,5671.52 J3.7@6343.52,5711 ; J8.16@6335,6045.01 J8.18@6285,6045.01 ; J8.12@6435,6045.01 J8.10@6485,6045.01 J8.8@6535,6045.01 ; U1.2@6517,6569.3 v2(6517,6602) ; J8.8@6535,6007.01 v2(6535,5932.02) 6601,5932.02 6635,5966.02 J8.4@6635,6045.01 ; C4.2@6543.5,6726.5 v2(6578.5,6726.5) ; C42.2@6651.5,6443.5 6650.99,6444 R73.1@6650.99,6505.5 v2(6689.5,6505.5) ; U7.2@8043,4757 8113.43,4757 ; C57.2@8148,4722.43 8113.43,4757 ; C58.2@8148,4782.57 8122.43,4757 8113.43,4757 ; C59.2@8796.43,4768 8798.43,4768 8829,4737.43 ; U8.2@8829,4648 8829,4737.43 ; C56.2@8858.57,4767 8829,4737.43
  Top Layer w20: J18.4@3322,4449 3369.5,4401.5 C2.2@3369.5,4358 C1.2@3369.5,4296 C70.2@3369.5,4234 ; 3677.47,5115.98 3768.45,5025 C61.2@3785.01,5025 ; 3677.47,5289.93 3759.54,5372 C64.2@3781.5,5372 ; 3680.43,5200 U2.3@3849.13,5200 3892,5200 3934.5,5157.5 C63.2@3938,5157.5 ; v2(3913,5404) 3946,5371 C62.2@3951,5371 ; v2(3950,4959) C60.2@3950,5006 ; C47.2@4269.43,6512 4253.2,6495.76 U4.5@4253.2,6452.4 v2(4284.4,6452.4) ; C45.2@4280,6303 4253.2,6329.8 U4.4@4253.2,6377.6 v2(4284.4,6377.6) ; R174.1@5485.22,4327.45 v3(5485.22,4357.78) ; C65.2@5622.23,1566.71 5769.2,1566.71 ; v3(5655.24,1776.72) R158.1@5687.47,1776.72 ; R175.1@5717.54,4331 v3(5743,4331) ; U14.3@5792.47,1499.79 5792.47,1543.44 ; v3(5923.92,1749.85) R157.1@5923.92,1779.52 ; C66.2@5934.75,1544.08 5912.12,1566.71 5815.74,1566.71 ; R159.1@6386.88,4318.16 v3(6386.88,4345.13) ; C68.2@6386.88,4561.42 6406.52,4541.78 6508.17,4541.78 ; C73.2@6519.52,1577.95 6664.4,1577.95 ; v3(6524.51,1786.44) R173.1@6554.99,1786.44 ; U15.3@6529.39,4600.8 6529.39,4563 ; R160.1@6627.19,4315.36 v3(6659.64,4315.36) ; U17.3@6689.91,1506.95 6689.91,1552.44 ; C67.2@6701.41,4541.78 6550.61,4541.78 ; v3(6795.5,1749.46) R172.1@6795.5,1779.55 ; C74.2@6832.52,1548.35 6802.93,1577.95 6715.41,1577.95 ; 5769.2,1566.71 5792.47,1543.44 ; 5769.2,1566.71 v3@5789.52,1566.71 ; v3@5789.52,1566.71 5815.74,1566.71 ; v3@5789.52,1566.71 v3(5792.47,1563.76) 5792.47,1543.44 ; 5792.47,1543.44 5815.74,1566.71 ; 6508.17,4541.78 6529.39,4563 ; 6508.17,4541.78 v3@6529.39,4541.78 ; v3@6529.39,4541.78 6550.61,4541.78 ; v3@6529.39,4541.78 6529.39,4563 ; 6529.39,4563 6550.61,4541.78 ; 6664.4,1577.95 v3@6690.52,1577.95 ; 6664.4,1577.95 6689.91,1552.44 ; 6689.91,1552.44 6715.41,1577.95 ; 6689.91,1552.44 6689.91,1577.33 v3@6690.52,1577.95 ; v3@6690.52,1577.95 6715.41,1577.95
  Top Layer w25: J16.23@5390,6229 v2(5390,6303) ; J16.19@5490,6229 v2(5490,6303) ; J16.13@5640,6229 v2(5640,6303) ; J16.9@5740,6229 v2(5740,6303)
  Top Layer w30: U2.6@3619.4,5202.95 U2.6@3622.43,5199.92 ; J16.25@5340,6229 J16.23@5390,6229 J16.21@5440,6229 J16.19@5490,6229 J16.17@5540,6229 ; C76.2@5455.22,4581.62 5485.84,4551 5572,4551 ; U18.3@5607.42,4604.45 v3@5607.42,4561.42 ; J16.13@5640,6229 J16.11@5690,6229 J16.9@5740,6229 J16.7@5790,6229 ; C75.2@5785.22,4550.44 v3@5618.39,4550.44 ; R60.2@9205,5020.15 9205.15,5020 v3(9257,5020) R61.2@9305,5020 ; 5572,4551 5597,4551 v3@5607.42,4561.42 ; 5572,4551 5572.56,4550.44 v3@5618.39,4550.44 ; v3@5607.42,4561.42 v3@5618.39,4550.44
  Bottom Layer w30: C12.2@4136.04,3868 C6.2@4203.05,3868 ; C13.2@4147.54,3008 v3(4179,3008) C7.2@4211.56,3008 ; v3(9257,5020) 9461,5020 ; D15.2@9485.53,4911 9486.53,4912 9486.53,4994.47 ; D17.2@9486.53,5084 9486.53,5045.53 ; 9461,5020 9486.53,4994.47 ; 9461,5020 9485.53,5020 9486.53,5019 ; 9461,5020 9486.53,5045.53 ; 9486.53,4994.47 9486.53,5019 ; 9486.53,5019 9486.53,5045.53
  other v3: 6687.52,1567.44 4169,3870 6530,4549 5609,4558 2664.6,5037 2692.6,5037 2719.73,5037 2692.36,5067 2663.6,5067.81 2720.6,5067.81
  other v5: 3593,5159.02 3635.24,5159 3593,5203 3635.24,5202.98 3593,5246.98 3635.24,5246.95
Batt+: F1.1 F1.2 J1.1 J1.2
Batt-: C8.2 C10.2 J2.1 J2.2 L7.2
CS3: D14.1 D16.1 J3.14 R60.1 R61.1 | length 3765.8
  Top Layer w8: J3.14@6249.03,5577.14 6249.03,5438.97 6389,5299 8740,5299 9125.15,4913.85 R60.1@9205,4913.85
  Top Layer w20: R60.1@9205,4913.85 9304.85,4913.85 R61.1@9305,4913.7 D14.1@9483.83,4913.7 ; D14.1@9486.53,4911 D14.1@9483.83,4913.7 ; D16.1@9486.53,5084 9486.53,4916.4 D14.1@9483.83,4913.7
CT1: D2.2 R14.1 T1.2 | length 178.8
  Top Layer w40: T1.2@7016,6820.09 7016,6740 D2.2@7025,6731 7094,6731 R14.1@7106,6719
CT2: R14.2 R56.1 R62.2 R68.1 T1.4 | length 925
  Top Layer w8: R56.1@6689.5,6660.5 6766.91,6660.5 R62.2@6780,6673.58
  Top Layer w40: R62.2@6780,6673.58 6784.47,6669.11 7106,6669.11 ; R68.1@6975,6474.99 7008.01,6508 7060,6508 7106,6554 7106,6669.11 ; T1.4@7216,6820.09 7216,6773.88 R14.2@7161.12,6719 7161.12,6680.12 7150.11,6669.11 7106,6669.11
CT_N: J16.6 R68.2 | length 1351.2
  Top Layer w25: J16.6@5840,6069 v2(5840,6143)
  Top Layer w40: v2(6975,6377) R68.2@6975,6412
  Signal Layer 1 w20: v2(5840,6143) 5840,6160.61 5956.39,6277 6843.77,6277 6911.82,6345.05 6943.05,6345.05 v2(6975,6377)
CT_P: J16.5 R74.2 | length 1206.7
  Top Layer w25: J16.5@5840,6229 v2(5840,6303)
  Top Layer w40: v2(6907,6377) R74.2@6907,6412
  Signal Layer 1 w20: v2(5840,6303) 6833,6303 v2(6907,6377)
Dbus+: C9.1 C46.1 C83.1 C84.1 C87.1 C88.1 C89.1 L7.4 R76.1 T1.11 | length 195.8
  Top Layer w20: R76.1@3623.17,6734 3623.17,6929.83
  other v1: 6627,7149 6053,7151 6573,7151 6753,7151 5943,7152 6167,7152 6397,7152 6508,7152 5999,7153 6699,7153 5889,7154 6113,7154 6279,7154 6343,7154 6454,7154 6225,7156 6573,7206 6625,7206 5999,7208 6051,7208 6699,7208 6751,7208 5889,7209 5941,7209 6113,7209 6165,7209 6343,7209 6395,7209 6454,7209 6506,7209 6225,7211 6277,7211 6624,7266 6050,7268 6570,7268 6750,7268 5940,7269 6164,7269 6394,7269 6505,7269 5996,7270 6696,7270 5886,7271 6110,7271 6276,7271 6340,7271 6451,7271 6222,7273 6570,7323 6622,7323 5996,7325 6048,7325 6696,7325 6748,7325 5886,7326 5938,7326 6110,7326 6162,7326 6340,7326 6392,7326 6451,7326 6503,7326 6222,7328 6274,7328
Earth: C5.2 C10.1
EMU0: J3.2
EMU1: J3.1
EN_1: J3.60 J16.15 J20.6 J21.6 | length 4437.8
  Top Layer w8: v2(5590,6155) 5615,6130 5615,5955 5649.55,5920.45 6428.75,5920.45 6444.2,5905 6636,5905 6665,5934 7088,5934 7119,5903 7119,5829 J21.6@7075,5785
  Top Layer w15: J3.60@5398.64,5577.14 v2(5398.64,5619.52)
  Top Layer w25: v2(5590,6155) J16.15@5590,6229
  Signal Layer 1 w8: v2(5398.64,5619.52) 5398.64,5963.64 v2(5590,6155)
  Signal Layer 2 w25: J21.6@7075,5785 7149,5711 8560,5711 8606,5757 8606,5807 8631,5832 8709,5832 J20.6@8756,5785
ERRORSTS: J3.117
G_1: D3.1 J4.1 R21.1 | length 207.3
  Top Layer w20: R21.1@7245,6162 7245,6102.69 D3.1@7263.69,6084 7263.69,5974.69 J4.1@7255,5966
G_2: D18.1 J6.1 R64.1 | length 207.3
  Top Layer w20: J6.1@7995,5966 8019.69,5990.69 D18.1@8019.69,6084 8011,6092.69 R64.1@8011,6159.44
G_3: D4.1 J9.1 R22.1 | length 203.3
  Top Layer w20: R22.1@8906,6156.88 8906,6111 D4.1@8933,6084 8933,5969 J9.1@8936,5966
G_4: D19.1 J11.1 R65.1 | length 211.2
  Top Layer w20: R65.1@9660,6161.44 9660,6111 D19.1@9687,6084 9687,5977 J11.1@9676,5966
HSEC_1V2: J3.119
HSEC_3V3: J3.118
HSEC_ADC-VREFHI: J3.45
HSEC_GPIO26: J3.79
HSEC_GPIO27: J3.81
Io_+: C24.1 C25.1 C26.1 C27.1 C28.1 C29.1 C30.1 C86.1 L1.2 L1.4 R1.2 R2.1 R3.1 R4.1 R5.1 R6.2 R7.2 R8.2 R9.2 R11.2 R40.2 R42.2 TP2.1 | length 2939.5
  Top Layer w15: 4740.56,1999 4775.56,1964 ; R1.2@4775.56,1667 4775.56,1964 ; 4807.56,1996 4775.56,1964 ; C26.1@4950,2037.43 4805.43,2037.43 4775.56,2007.56 4775.56,1964
  Top Layer w20: 4285.5,4242.5 4422,4379 v3(4422,4537) ; TP2.1@4327,4982 4432.5,4876.5 R40.2@4432.5,4873 4432.5,4808 ; v2(4432.5,4673.5) 4432.5,4808 ; R42.2@4561.5,4808 4432.5,4808 ; C25.1@4255.61,4163.23 4282,4189.62 4282,4239 4255.61,4212.61 C25.1@4255.61,4163.23
  Signal Layer 1 w20: v3(4422,4537) 4422,4662.99 v2(4432.5,4673.5)
  Bottom Layer w15: R2.1@4218,2452.44 4218,2399 4249.5,2367.5 v1(4316,2367.5) ; R5.1@4222,3723.44 4222,3667 4250,3639 v1(4316,3639) ; R4.1@4226,3305.44 4226,3240 4252,3214 v1(4316,3214) ; R3.1@4229,2880 4229,2819 4257,2791 v1(4318,2791)
  Bottom Layer w30: C86.1@4144,4201.83 4217.02,4201.83 C25.1@4255.61,4163.23 ; C27.1@4384.39,2037.54 4424.84,1997.09 C30.1@4496,1997.09 ; C28.1@4680,4192.83 4772.17,4192.83 C24.1@4800.06,4164.94 ; C26.1@4940.69,2038.79 4983.39,1996.09 C29.1@5052,1996.09
  other v1: 4316,2268 4367,2268 4316,2317.75 4367,2317.75 4367,2367.5 4316,2417.25 4367,2417.25 4316,2467 4367,2467 4318,2691.5 4369,2691.5 4828,2733.5 4882,2735.5 4933,2735.5 4984,2735.5 5035,2735.5 5085,2735.5 5136,2735.5 5187,2735.5 5238,2735.5 4318,2741.25 4369,2741.25 4828,2783.25 4882,2785.25 4933,2785.25 4984,2785.25 5035,2785.25 5085,2785.25 5136,2785.25 5187,2785.25 5238,2785.25 4369,2791 4828,2833 4882,2835 4933,2835 4984,2835 5035,2835 5085,2835 5136,2835 5187,2835 5238,2835 4318,2840.75 4369,2840.75 4828,2882.75 4882,2884.75 4933,2884.75 4984,2884.75 5035,2884.75 5085,2884.75 5136,2884.75 5187,2884.75 5238,2884.75 4318,2890.5 4369,2890.5 4828,2932.5 4882,2934.5 4933,2934.5 4984,2934.5 5035,2934.5 5085,2934.5 5136,2934.5 5187,2934.5 5238,2934.5 4828,2984.5 4882,2986.5 4933,2986.5 4984,2986.5 5035,2986.5 5085,2986.5 5136,2986.5 5187,2986.5 5238,2986.5 4828,3034.25 4882,3036.25 4933,3036.25 4984,3036.25 5035,3036.25 5085,3036.25 5136,3036.25 5187,3036.25 5238,3036.25 4316,3114.5 4367,3114.5 4316,3164.25 4367,3164.25 4367,3214 4316,3263.75 4367,3263.75 4316,3313.5 4367,3313.5 4814,3365.5 4868,3367.5 4919,3367.5 4970,3367.5 5021,3367.5 5071,3367.5 5122,3367.5 5173,3367.5 5224,3367.5 4814,3415.25 4868,3417.25 4919,3417.25 4970,3417.25 5021,3417.25 5071,3417.25 5122,3417.25 5173,3417.25 5224,3417.25 4814,3465 4868,3467 4919,3467 4970,3467 5021,3467 5071,3467 5122,3467 5173,3467 5224,3467 4814,3514.75 4868,3516.75 4919,3516.75 4970,3516.75 5021,3516.75 5071,3516.75 5122,3516.75 5173,3516.75 5224,3516.75 4316,3539.5 4367,3539.5 4814,3564.5 4868,3566.5 4919,3566.5 4970,3566.5 5021,3566.5 5071,3566.5 5122,3566.5 5173,3566.5 5224,3566.5 4316,3589.25 4367,3589.25 4814,3616.5 4868,3618.5 4919,3618.5 4970,3618.5 5021,3618.5 5071,3618.5 5122,3618.5 5173,3618.5 5224,3618.5 4367,3639 4814,3666.25 4868,3668.25 4919,3668.25 4970,3668.25 5021,3668.25 5071,3668.25 5122,3668.25 5173,3668.25 5224,3668.25 4316,3688.75 4367,3688.75 4316,3738.5 4367,3738.5
Ipri: C41.1 J3.25 R58.2 R59.1 | length 1143.9
  Top Layer w8: v2(6060,5957) v2@6060.06,5956.94 ; v2@6060.06,5955 v2@6060.06,5956.94 ; R59.1@6158.5,6569 6158.99,6569.5 R58.2@6224.51,6569.5 ; C41.1@6224,6633.5 6224,6570 R58.2@6224.51,6569.5 ; v2@6060.06,5956.94 6060.06,6405.05 R58.2@6224.51,6569.5
  Top Layer w15: v2(6060.06,5668.62) J3.25@6060.06,5711
  Signal Layer 2 w8: v2(6060,5957) 6060,5668.68 v2(6060.06,5668.62)
ISO_5V: C43.1 C49.1 R75.2 U3.5 U5.1 | length 372.4
  Top Layer w8: R75.2@3284.01,6376 3342.87,6434.86 U3.5@3342.87,6456.6
  Top Layer w20: U5.1@3104,6525.57 3184.93,6525.57 C49.1@3185,6525.5 3273.97,6525.5 U3.5@3342.87,6456.6
isoGND: C9.2 C43.2 C46.2 C48.2 C49.2 C51.2 C83.2 C84.2 C87.2 C88.2 C89.2 D20.2 D23.2 L7.3 Q16.2 Q17.2 R80.1 T10.5 U3.3 U3.4 U5.3 U5.4 | length 1711.3
  Top Layer w20: C9.2@2307,6799.81 2373.81,6733 R80.1@2914.91,6733 2859.07,6677.16 C51.2@2859.07,6634 2954,6539.07 U5.4@2954,6525.57 ; v4(2915.43,6525.57) U5.4@2954,6525.57 ; v4(3214,6397) C43.2@3262,6445 3244.5,6462.5 C49.2@3185,6462.5 3034.5,6462.5 3004,6493 U5.3@3004,6525.57 U5.4@2954,6525.57 ; U3.4@3342.87,6531.4 v4(3387.6,6531.4) ; U3.3@3451.13,6531.4 v4(3495.6,6531.4) ; v4(3458.31,6335.31) D23.2@3458.31,6374 ; v4(3619,6361) 3619,6385 C48.2@3648,6414 ; v4(3620,6467) 3620,6442 C48.2@3648,6414 ; T10.5@3729,6415 3728,6414 C48.2@3648,6414
  other v1: 6570,7787 5996,7789 6516,7789 6696,7789 5886,7790 6110,7790 6340,7790 6451,7790 5942,7791 6642,7791 5832,7792 6056,7792 6222,7792 6286,7792 6397,7792 6168,7794 6516,7844 6568,7844 5942,7846 5994,7846 6642,7846 6694,7846 5832,7847 5884,7847 6056,7847 6108,7847 6286,7847 6338,7847 6397,7847 6449,7847 6168,7849 6220,7849 6567,7904 5993,7906 6513,7906 6693,7906 5883,7907 6107,7907 6337,7907 6448,7907 5939,7908 6639,7908 5829,7909 6053,7909 6219,7909 6283,7909 6394,7909 6165,7911 6513,7961 6565,7961 5939,7963 5991,7963 6639,7963 6691,7963 5829,7964 5881,7964 6053,7964 6105,7964 6283,7964 6335,7964 6394,7964 6446,7964 6165,7966 6217,7966
MCU_GPIO0: J3.49
MCU_GPIO1: J3.51
MCU_GPIO2: J3.53
MCU_GPIO3: J3.55
MCU_GPIO4: J3.50
MCU_GPIO5: J3.52
MCU_GPIO14: J3.62
MCU_GPIO15: J3.64
MCU_GPIO16: J3.67 J13.2 | length 567.8
  Top Layer w8: J13.2@5063,6191.96 5063,6026 5272.65,5816.35 J3.67@5272.65,5711
MCU_GPIO17: J3.69 J13.3 | length 532.8
  Top Layer w8: J13.3@4963,6077 4963,5992 5009,5946 5097,5946 5241.16,5801.84 J3.69@5241.16,5711
MCU_GPIO18: J3.71 J13.4 | length 693.1
  Top Layer w8: J13.4@4863,6191.96 4863,6029 4977,5915 5094,5915 5209.66,5799.34 J3.71@5209.66,5711
MCU_GPIO19: J3.73 J13.5 | length 688.5
  Top Layer w8: J13.5@4763,6077 4763,5962 4848,5877 5105,5877 5178.17,5803.83 J3.73@5178.17,5711
MCU_GPIO20: J3.68
MCU_GPIO21: J3.70
MCU_GPIO22: J3.72
MCU_GPIO23: J3.74
MCU_GPIO24: J3.75
MCU_GPIO25: J3.77
MCU_GPIO28: J3.76
MCU_GPIO29: J3.78
MCU_GPIO30: J3.80
MCU_GPIO31: J3.82
MCU_GPIO32: D22.1 J3.85 | length 616.7
  Top Layer w8: D22.1@4545,5985 4686,5844 4957,5844 4989.19,5811.81 J3.85@4989.19,5711
MCU_GPIO33: J3.87
MCU_GPIO34: J3.86
MCU_GPIO35: J14.121
MCU_GPIO36: J14.122
MCU_GPIO37: J14.123
MCU_GPIO38: J14.124
MCU_GPIO39: J3.88
MCU_GPIO40: J3.89
MCU_GPIO41: J3.91
MCU_GPIO45: J3.92
MCU_GPIO48: J3.99
MCU_GPIO49: J3.101
MCU_GPIO50: J3.103
MCU_GPIO51: J3.105
MCU_GPIO52: J3.107
MCU_GPIO53: J3.109
MCU_GPIO54: J3.100
MCU_GPIO55: J3.102
MCU_GPIO56: J3.104
MCU_GPIO57: J3.106
MCU_GPIO58: J3.108
MCU_GPIO59: J3.110
MCU_GPIO60: J14.125
MCU_GPIO61: J14.126
MCU_GPIO62: J14.127
MCU_GPIO63: J14.128
MCU_GPIO64: J14.129
MCU_GPIO65: J14.130
MCU_GPIO66: J14.131
MCU_GPIO67: J14.132
MCU_GPIO68: J14.133
MCU_GPIO69: J14.134
MCU_GPIO70: J14.137
MCU_GPIO71: J14.138
MCU_GPIO72: J14.139
MCU_GPIO73: J14.140
MCU_GPIO74: J14.141
MCU_GPIO76: J14.143
MCU_GPIO77: J14.144
MCU_GPIO78: J14.145
MCU_GPIO79: J14.146
MCU_GPIO80: J14.147
MCU_GPIO81: J14.148
MCU_GPIO82: J14.149
MCU_GPIO83: J14.150
MCU_GPIO84: J14.151
MCU_GPIO85: J14.152
MCU_GPIO86: J14.153
MCU_GPIO87: J14.154
MCU_GPIO88: J14.155
MCU_GPIO89: J14.156
MCU_GPIO90: J14.159
MCU_GPIO91: J14.160
MCU_GPIO92: J14.161
MCU_GPIO93: J14.162
MCU_GPIO94: J14.163
MCU_GPIO95: J14.168
MCU_GPIO96: J3.93
MCU_GPIO97: J3.94
MCU_GPIO98: J3.95
MCU_GPIO99: J3.96
MCU_GPIO104: J14.169
MCU_GPIO107: J14.170
MCU_GPIO125: J3.90
MCU_GPIO126: J14.142
MCU_GPIO127: J14.165
MCU_GPIO128: J14.166
MCU_GPIO133: J14.164
MCU_GPIO147: J14.167
MCU_TCK: J3.5 J8.9 J8.11 | length 774
  Top Layer w8: J8.11@6435,6258 J8.9@6485,6258
  Top Layer w15: v2(6375.02,5668.62) J3.5@6375.02,5711 ; v2(6485,6183.01) J8.9@6485,6258
  Signal Layer 1 w8: v2(6375.02,5668.62) 6318.65,5724.99 6318.65,6016.65 v2(6485,6183.01)
MCU_TDI: J3.8 J8.3 | length 964.4
  Top Layer w15: J3.8@6343.52,5577.14 v2(6343.52,5619.52) ; v2(6635,6183.01) J8.3@6635,6258
  Signal Layer 1 w8: v2(6343.52,5619.52) 6302.77,5660.26 6302.77,6035.96 6474.7,6207.88 6610.13,6207.88 v2(6635,6183.01)
MCU_TDO: J3.6 J8.7 | length 984.5
  Top Layer w15: v2(6375.02,5469.2) J3.6@6375.02,5577.14 ; v2(6535,6183.01) J8.7@6535,6258
  Signal Layer 1 w8: v2(6375.02,5469.2) 6375.02,5633.44 6399.89,5658.32 6399.89,5737.11 6374,5763 6374,6022.01 v2(6535,6183.01)
MCU_TMS: J3.3 J8.1 | length 662.4
  Top Layer w15: J3.3@6406.51,5711 v2(6406.51,5818.95) ; v2(6685,6183.01) J8.1@6685,6258
  Signal Layer 1 w8: v2(6406.51,5818.95) 6406.51,5866.52 6644.44,6104.45 6644.44,6142.45 v2(6685,6183.01)
MCU_TRSTn: J3.4 J8.2 | length 734.7
  Top Layer w15: J3.4@6406.51,5577.14 v2(6406.51,5619.52) ; J8.2@6685,6045.01 v2(6685,6120)
  Signal Layer 1 w8: v2(6406.51,5619.52) 6433,5646.01 6433,5870.56 6682.44,6120 v2(6685,6120)
MCU_XRSn: J3.120
NetC3_1: C3.1 R41.2 R58.1 U1.1 | length 193.4
  Top Layer w8: R58.1@6287.5,6569.5 6289,6571 C3.1@6354,6571 R41.2@6417,6571 6418.7,6569.3 U1.1@6479.6,6569.3
NetC3_2: C3.2 R41.1 R56.2 U1.4 | length 293.9
  Top Layer w8: C3.2@6354,6633.99 R41.1@6417,6633.99 6523.52,6633.99 6554.4,6664.87 U1.4@6554.4,6669.69 6617.31,6669.69 R56.2@6626.5,6660.5
NetC5_1: C5.1 C8.1 F1.3 F1.4 L7.1
NetC6_1: C6.1 C7.1 C11.1 R2.2 R3.2 R4.2 R5.2 R10.2 | length 2112.1
  Top Layer w15: R10.2@3780.56,4163 3781,4162.56 C11.1@3830,4162.56 v2(3864.12,4162.56)
  Bottom Layer w15: v2(3864.12,4162.56) 3971.48,4162.56 C6.1@4266.04,3868 4266.04,3822.6 R5.2@4222,3778.56 4189.89,3746.45 4189.89,3396.67 R4.2@4226,3360.56 4191,3325.56 4191,3091.55 C7.1@4274.55,3008 4274.55,2980.67 R3.2@4229,2935.12 4223.12,2935.12 4192,2904 4192,2533.56 R2.2@4218,2507.56
NetC11_2: C11.2 C12.1 C13.1 R13.2 R15.2 R17.2 R18.2 R20.2 | length 1985.7
  Top Layer w15: R13.2@3780.12,4108 3829.44,4108 C11.2@3830,4107.44 v2(3864.56,4107.44)
  Bottom Layer w15: v2(3864.56,4107.44) 3971.56,4107.44 4073.05,4005.95 C12.1@4073.05,3868 4073.05,3829.95 R15.2@4125,3778 4162,3741 4162,3393.56 R17.2@4130,3361.56 4140.44,3361.56 4166,3336 4166,3086.59 4112.48,3033.07 4112.48,3032.48 4088,3008 C13.1@4084.55,3008 4084.55,2979.57 R18.2@4129,2935.12 4161.11,2903.01 4161.11,2543.67 R20.2@4126,2508.56
NetC16_2: C16.2 C20.2 R27.2 R28.2 R29.2 | length 501.4
  Top Layer w30: C16.2@7008.04,4778.79 7008.04,4670.43 C20.2@7006.4,4668.79 7006.4,4539.98 R29.2@7006.04,4539.62 R28.2@7006.04,4409.62 7006.04,4283 R27.2@7009.43,4279.62
NetC17_2: C17.2 C21.2 R30.2 R31.2 R32.2 | length 518.4
  Top Layer w30: C17.2@6209,4780.91 6225.51,4764.41 C21.2@6225.51,4680.79 ; C21.2@6215,4691.29 C21.2@6225.51,4680.79 ; R32.2@6272.23,4304.73 6272.23,4434.56 R31.2@6273.67,4436 R30.2@6273.67,4566.97 6273.67,4632.63 C21.2@6225.51,4680.79
NetC18_2: C18.2 C22.2 R33.2 R34.2 R35.2 | length 523
  Top Layer w30: R35.2@6035.87,4304.73 R34.2@6035.87,4437 6035,4437.87 R33.2@6035,4567 6035,4661.26 C22.2@6015.48,4680.79 6015.48,4688.39 C18.2@6108,4780.91
NetC19_2: C19.2 C23.2 R36.2 R37.2 R38.2 | length 508.6
  Top Layer w40: R36.2@5117.91,4197.45 R37.2@5117.91,4327.45 R38.2@5117.91,4457.45 5138.53,4478.07 C23.2@5138.53,4578.72 ; C19.2@5138.53,4691.2 C23.2@5138.53,4578.72 ; C23.2@5143,4574.25 C23.2@5138.53,4578.72
NetC31_2: C31.2 C35.2 R44.2 R45.2 R46.2 | length 455.9
  Top Layer w30: C31.2@5126.52,1554.44 5127.61,1555.53 C35.2@5233.52,1555.53 5241.44,1547.61 R44.2@5318.29,1547.61 R45.2@5318.29,1677.61 R46.2@5318.29,1807.96
NetC32_2: C32.2 C36.2 R47.2 R48.2 R49.2 | length 532.5
  Top Layer w20: R47.2@6035.12,1788.61 R48.2@6035.12,1658.61 R49.2@6035.12,1528.61 6035.12,1433.02 C36.2@6059.91,1408.23 6059.91,1331.14 C32.2@6105.73,1285.32
NetC33_2: C33.2 C37.2 R50.2 R51.2 R52.2 | length 538.5
  Top Layer w30: C37.2@6213.91,1285.32 6285.7,1357.1 C33.2@6285.7,1408.23 6273.29,1420.63 R52.2@6273.29,1528.61 R51.2@6273.29,1658.61 R50.2@6273.29,1788.96
NetC34_2: C34.2 C38.2 R53.2 R54.2 R55.2 | length 526.2
  Top Layer w30: C38.2@7180.22,1407.69 C34.2@7180.22,1514.69 7180.22,1544.69 7199.24,1563.71 R53.2@7199.24,1634.07 R55.2@7199.24,1926
NetC42_1: C42.1 R66.1 R67.2 R73.2 U1.3 | length 267.5
  Top Layer w8: R66.1@6523,6505.5 6554.4,6536.9 ; C42.1@6588.5,6443.5 6588,6444 R73.2@6588,6505.5 6556.6,6536.9 6554.4,6536.9 ; R67.2@6628.39,6582.5 6563.5,6582.5 6554.4,6573.4 U1.3@6554.4,6569.3 6554.4,6536.9
NetC48_1: C48.1 D21.1 D27.1 U3.1 | length 327.7
  Top Layer w20: U3.1@3451.13,6456.6 3493.13,6456.6 D27.1@3546.53,6510 3546.53,6435.47 C48.1@3568,6414 3545.53,6391.53 D21.1@3545.53,6318
NetC51_1: C51.1 R79.2 U5.2 | length 170.6
  Top Layer w20: C51.1@2992.93,6634 3052.5,6634 R79.2@3053.5,6635 3053.5,6526.06 U5.2@3054,6525.57
NetC52_1: C52.1 R81.2 R83.1 U6.1 | length 196.2
  Top Layer w8: U6.1@5941.4,5278.13 5947.26,5283.99 R81.2@6010,5283.99 6010.5,5283.5 C52.1@6072,5283.5 R83.1@6135,5283.5
NetC52_2: C52.2 R81.1 R84.2 U6.4 | length 312.3
  Top Layer w8: R84.2@5791,5190 5855,5190 U6.4@5866.6,5178.4 ; U6.4@5866.6,5169.87 U6.4@5866.6,5178.4 ; C52.2@6072,5220.5 6071.5,5221 R81.1@6010,5221 5909,5221 5866.6,5178.6 U6.4@5866.6,5178.4
NetC55_1: C55.1 R93.2 R94.2 U6.3 | length 221.7
  Top Layer w8: R93.2@5791.5,5253 5849,5253 5866.6,5270.6 U6.3@5866.6,5278.13 5866.6,5342.91 R94.2@5864.5,5345 C55.1@5800.5,5345
NetC64_1: C64.1 U2.5 | length 73.9
  Top Layer w30: C64.1@3844.5,5372 3849.13,5367.37 U2.5@3849.13,5300
NetC65_1: C65.1 C66.1 L3.2 U14.6 | length 547.1
  Top Layer w20: L3.2@5554.52,1629.94 5554.76,1629.7 C65.1@5622.23,1629.7 5768.73,1629.7 ; U14.6@5792.47,1714.35 5792.47,1653.44 ; 5818.52,1629.7 5816.21,1629.7 ; C66.1@5934.75,1658.25 5906.2,1629.7 5816.21,1629.7 ; 5768.73,1629.7 5790.52,1629.7 ; 5768.73,1629.7 5792.47,1653.44 ; 5790.52,1629.7 5816.21,1629.7 ; 5790.52,1629.7 5792.47,1631.65 5792.47,1653.44 ; 5792.47,1653.44 5816.21,1629.7
NetC67_1: C67.1 C68.1 L4.2 U15.6 | length 558.5
  Top Layer w15: 6497,4478.79 6501.61,4478.79 6529.39,4451 ; 6529,4478.79 6529.39,4478.39 6529.39,4451 ; U15.6@6529.39,4386.23 6529.39,4451 ; 6552,4478.79 6552,4473.61 6529.39,4451
  Top Layer w30: C68.1@6386.88,4447.25 6418.42,4478.79 6497,4478.79 ; 6501.61,4478.79 6529,4478.79 6552,4478.79 C67.1@6701.41,4478.79 6762.72,4478.79 L4.2@6763,4478.5
NetC69_1: C69.1 R82.2 R84.1 | length 131.3
  Top Layer w8: R82.2@5597.99,5190 5599.5,5191.5 C69.1@5664,5191.5 5665.5,5190 R84.1@5728.01,5190
NetC69_2: C69.2 R85.2 R93.1 | length 131.8
  Top Layer w8: R85.2@5597.99,5253 5662.5,5253 C69.2@5664,5254.5 5727.01,5254.5 R93.1@5728.5,5253
NetC73_1: C73.1 C74.1 L5.2 U17.6 | length 559.2
  Top Layer w20: C73.1@6519.52,1640.94 6670.41,1640.94 ; U17.6@6689.91,1721.52 6689.91,1660.44 ; L5.2@6924.52,1639.94 6901.93,1662.53 C74.1@6832.52,1662.53 6810.93,1640.94 6709.41,1640.94 ; 6670.41,1640.94 6689.52,1640.94 ; 6670.41,1640.94 6689.91,1660.44 ; 6689.52,1640.94 6709.41,1640.94 ; 6689.52,1640.94 6689.91,1641.33 6689.91,1660.44 ; 6689.91,1660.44 6709.41,1640.94
NetC75_1: C75.1 C76.1 L6.2 U18.6 | length 612.7
  Top Layer w15: 5579,4487.45 5580.97,4487.45 5607.42,4461 ; 5606,4487.45 5607.42,4486.03 5607.42,4461 ; 5633.56,4487.45 5633.56,4487.15 5607.42,4461
  Top Layer w25: U18.6@5607.42,4389.88 5607.42,4461
  Top Layer w30: L6.2@5364,4492.5 5389.06,4467.45 C76.1@5455.22,4467.45 5475.22,4487.45 5579,4487.45 ; 5580.97,4487.45 5606,4487.45 5633.56,4487.45 C75.1@5785.22,4487.45
NetD1_2: D1.2 R1.1 | length 57.4
  Top Layer w15: D1.2@4663,1667 R1.1@4720.44,1667
NetD2_1: D2.1 R62.1 R67.1 R74.1 | length 445.3
  Top Layer w8: R67.1@6691.39,6582.5 6756.91,6582.5 R62.1@6780,6559.41
  Top Layer w40: R62.1@6780,6559.41 6907,6559.41 ; R74.1@6907,6474.99 6907,6559.41 ; D2.1@7025,6602.06 6982.35,6559.41 6907,6559.41
NetD3_2: D3.2 R23.1 | length 80.8
  Top Layer w20: D3.2@7350.31,6084 7359.56,6093.25 R23.1@7359.56,6161
NetD4_2: D4.2 R24.1 | length 77.1
  Top Layer w20: R24.1@9017,6160 9017,6086.61 D4.2@9019.61,6084
NetD5_1: D5.1 Q1.1 Q2.1 T1.12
